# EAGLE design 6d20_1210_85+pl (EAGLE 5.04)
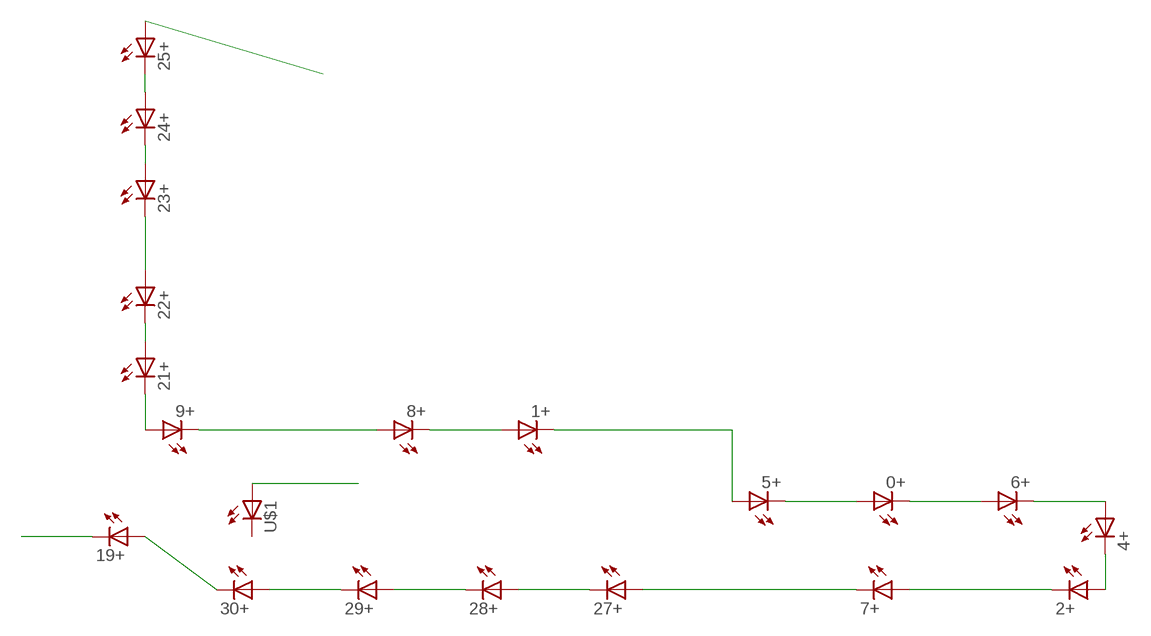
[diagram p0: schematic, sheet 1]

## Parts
0+  LED1210  [1210]
1+  LED1210  [1210]
2+  LED1210  [1210]
4+  LED1210  [1210]
5+  LED1210  [1210]
6+  LED1210  [1210]
7+  LED1210  [1210]
8+  LED1210  [1210]
9+  LED1210  [1210]
19+  LED1210  [1210]
21+  LED1210  [1210]
22+  LED1210  [1210]
23+  LED1210  [1210]
24+  LED1210  [1210]
25+  LED1210  [1210]
27+  LED1210  [1210]
28+  LED1210  [1210]
29+  LED1210  [1210]
30+  LED1210  [1210]
U$1  LED  [P-LCC4-MINI]

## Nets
ANODE: U$1.P$3(A)
MINUS: 19+.P$2(C)
N$4: 19+.P$1(A) 30+.P$2(C)
N$6: 8+.P$1(A) 9+.P$2(C)
N$7: 29+.P$2(C) 30+.P$1(A)
N$8: 28+.P$2(C) 29+.P$1(A)
N$9: 27+.P$2(C) 28+.P$1(A)
N$12: 2+.P$2(C) 7+.P$1(A)
N$13: 7+.P$2(C) 27+.P$1(A)
N$14: 2+.P$1(A) 4+.P$2(C)
N$15: 4+.P$1(A) 6+.P$2(C)
N$16: 0+.P$2(C) 6+.P$1(A)
N$17: 0+.P$1(A) 5+.P$2(C)
N$19: 1+.P$2(C) 5+.P$1(A)
N$20: 1+.P$1(A) 8+.P$2(C)
N$23: 9+.P$1(A) 21+.P$2(C)
N$24: 21+.P$1(A) 22+.P$2(C)
N$25: 22+.P$1(A) 23+.P$2(C)
N$26: 24+.P$1(A) 25+.P$2(C)
N$28: 23+.P$1(A) 24+.P$2(C)
PLUS: 25+.P$1(A)
Unconnected: U$1.P$1(C)

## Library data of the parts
0+ 1+ 2+ 4+ 5+ 6+ 7+ 8+ 9+ 19+ 21+ 22+ 23+ 24+ 25+ 27+ 28+ 29+ 30+ U$1 = led(2):LED: LED

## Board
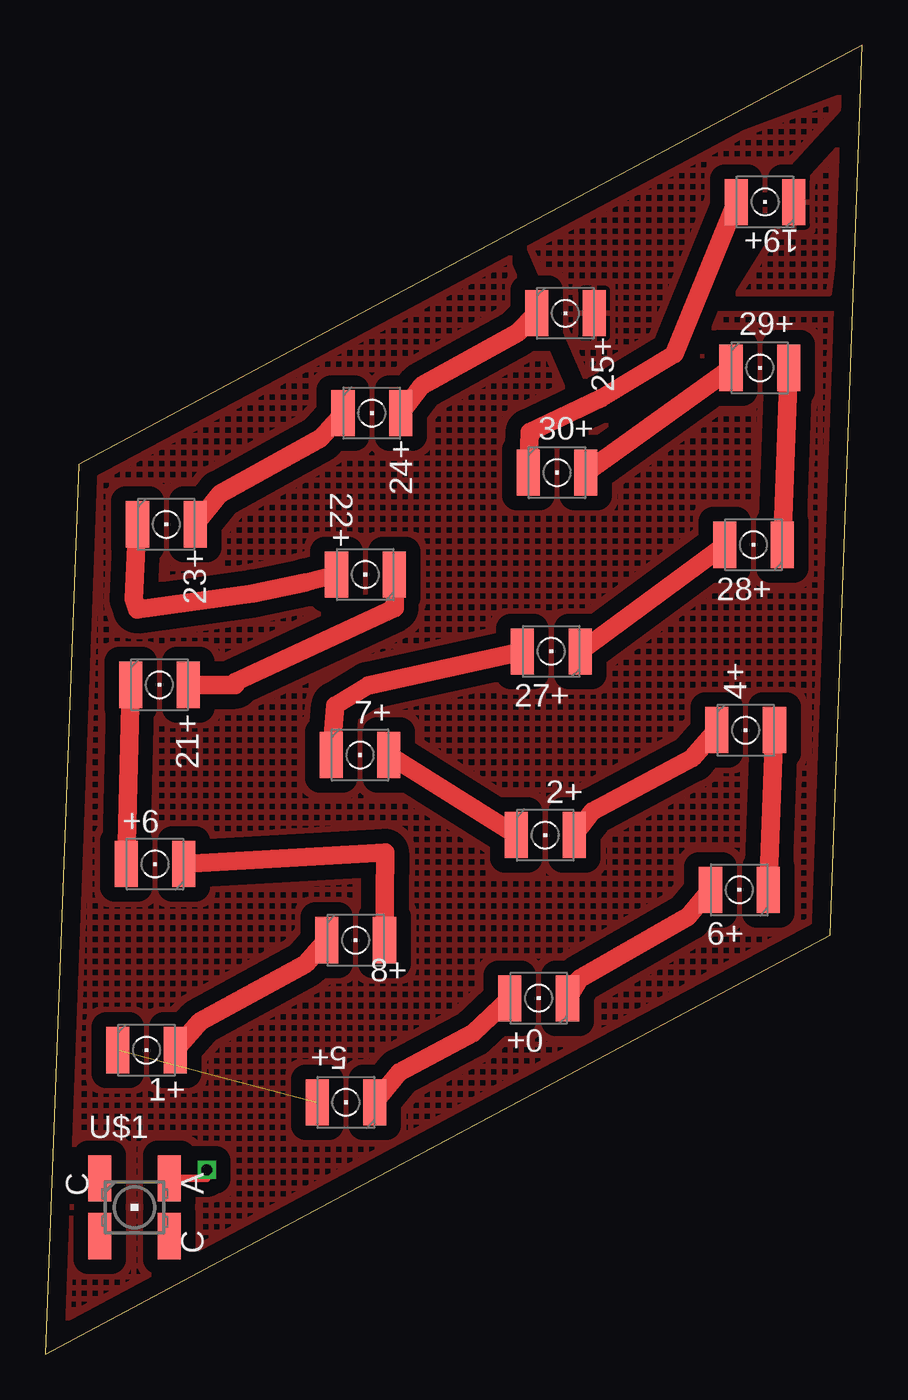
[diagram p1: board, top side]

Size 45 x 72.11 mm. Coordinates in mm from the lower left corner, seen from the top.
Outline: 0,0 43.22,23.09 45,72.11 1.83,49.01 0,0
Copper layers (1*16): Top 0.035mm / dielectric 1.5mm / Bottom 0.035mm
Design rules "default": minimum track width 10mil, minimum drill 24mil, track to track 8mil, track to pad 8mil, pad to pad 8mil, via to via 8mil, smd to smd 8mil, copper to edge 40mil, drill to drill 8mil, minimum pad ring 10mil, minimum via ring 8mil, stop-mask expansion 4mil, vias tented up to drill 0mil, thermal gap 10mil

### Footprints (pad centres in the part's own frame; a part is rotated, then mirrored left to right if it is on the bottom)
1210 = smd 1.27 x 2.54: P$1 1.587,0; P$2 -1.587,0
P-LCC4-MINI = smd 2.54 x 1.27: P$1 1.587,-1.905; P$2 -1.587,-1.905; P$3 -1.587,1.905; P$4 1.587,1.905

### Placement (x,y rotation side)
0+  27.17,19.61 180 top
1+  5.57,16.75 0 top
2+  27.53,28.6 0 top
4+  38.57,34.38 0 top
5+  16.55,13.87 180 top
6+  38.22,25.58 180 top
7+  17.33,33.01 0 top
8+  17.09,22.81 0 top
9+  6.04,27 180 top
19+  39.64,63.48 180 top
21+  6.28,36.88 0 top
22+  17.62,42.95 180 top
23+  6.66,45.72 0 top
24+  17.98,51.85 0 top
25+  28.64,57.35 0 top
27+  27.86,38.72 180 top
28+  39,44.59 180 top
29+  39.35,54.34 0 top
30+  28.18,48.57 0 top
U$1  4.91,8.09 270 top

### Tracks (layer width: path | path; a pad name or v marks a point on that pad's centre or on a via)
ANODE  (via drill 0.6)
  Top 0.406: U$1.P$3 8.89,9.68 v8.89,10.16
MINUS
  pour Top (isolate 0.813, rank 2, hatched): 44.45,68.58 38.1,58.42 43.18,58.42
N$1
  pour Top (isolate 0.813, rank 3, hatched): 2.54,49.53 0,0 43.18,24.13 44.45,71.12
N$4
  Top 1.016: 30+.P$2 26.67,50.8 30.62,52.68 34.65,55.11 19+.P$1
N$6
  Top 1.016: 8+.P$1 18.71,27.63 9+.P$2
N$7
  Top 1.016: 30+.P$1 29+.P$2
N$8
  Top 1.016: 28+.P$2 29+.P$1
N$9
  Top 1.016: 27+.P$2 28+.P$1
N$12
  Top 1.016: 7+.P$1 2+.P$2
N$13
  Top 1.016: 7+.P$2 15.97,35.74 17.78,36.83 27+.P$1
N$14
  Top 1.016: 2+.P$1 30.13,29.91 35.63,32.84 4+.P$2
N$15
  Top 1.016: 6+.P$2 4+.P$1
N$16
  Top 1.016: 0+.P$2 29.41,20.67 35.41,24.11 6+.P$1
N$17
  Top 1.016: 5+.P$2 19.5,15.53 23.56,17.69 0+.P$1
N$19  (1 unrouted)
N$20
  Top 1.016: 1+.P$1 8.53,18.33 14.33,21.51 8+.P$2
N$23
  Top 1.016: 9+.P$1 21+.P$2
N$24
  Top 1.016: 21+.P$1 10.45,36.88 10.45,37.02 19.23,41.12 19.23,42.95 22+.P$2
N$25
  Top 1.016: 22+.P$1 14.32,42.52 11.43,41.91 5.05,41.03 4.86,41.61 23+.P$2
N$26
  Top 1.016: 24+.P$1 20.73,53.36 26.03,56.29 25+.P$2
N$28
  Top 1.016: 23+.P$1 9.61,47.4 15.16,50.46 24+.P$2
PLUS
  pour Top (isolate 0.813, hatched): 44.61,69.59 35.25,59.32 34.13,55.04 29.91,53.46 25.94,62.61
